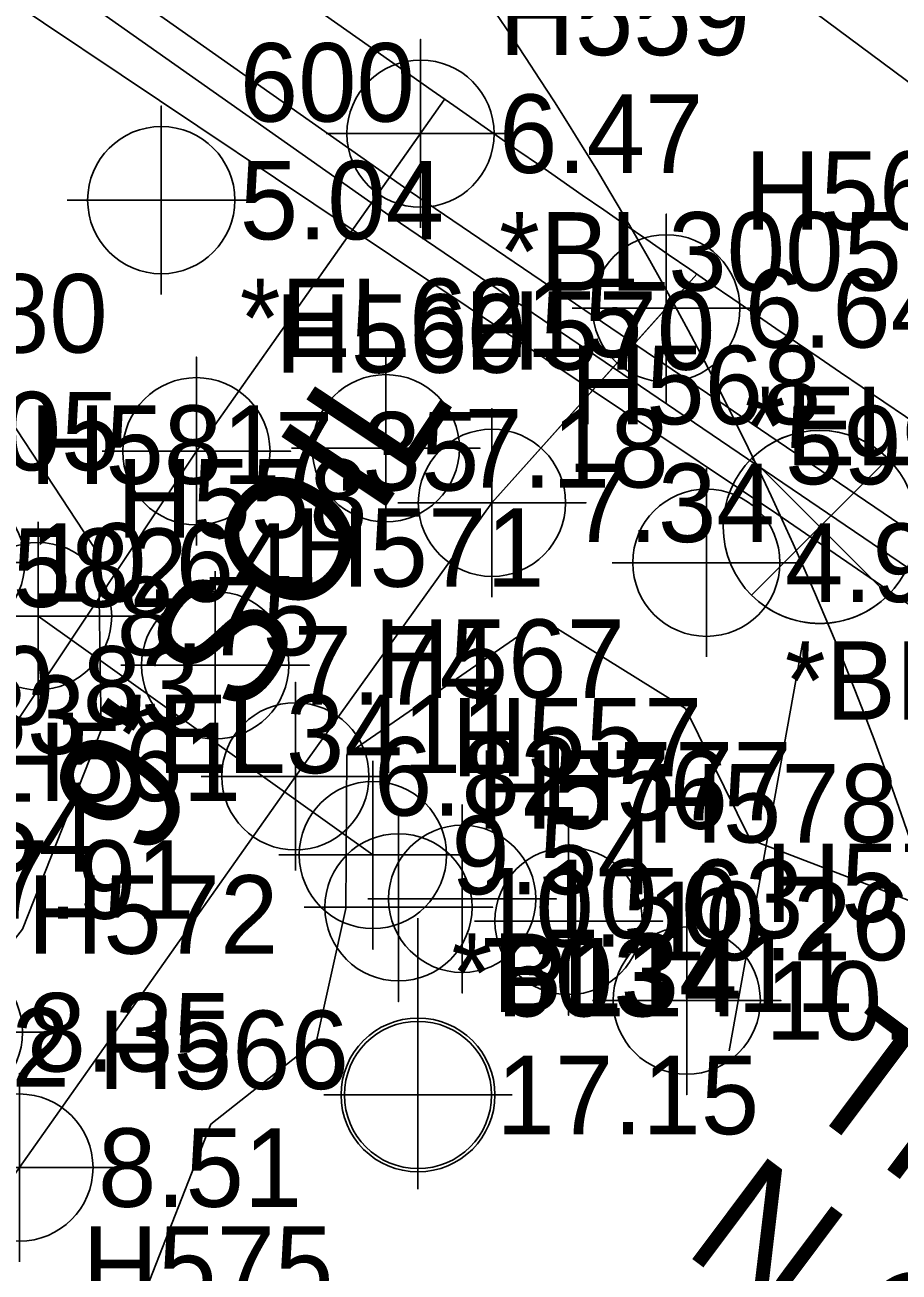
# Model space of a CAD drawing. Extents: x 2597630 to 2605918, y 617194 to 635093.
# Drawn here: x 2605052.23 to 2605080.06, y 618492.94 to 618532.66 of the extents above; entities that cross this region are included whole.
import ezdxf

# ---------------------------------------------------------------- set-up
doc = ezdxf.new("R2010")
doc.units = 0
for name, color, linetype in [('COGO Default Chain', 7, 'Continuous'), ('COGO Default Curve', 7, 'Continuous'), ('Cogo Default Point CELL', 7, 'Continuous'), ('COGO Default Point Number', 7, 'Continuous'), ('Default Symbol Text', 7, 'Continuous'), ('Exist DTM Regular Point CELL', 7, 'Continuous'), ('Exist DTM Regular Point Cogo Elevation', 7, 'Continuous'), ('Exist DTM Regular Point Cogo Number', 7, 'Continuous'), ('Exist Horizontal Alignment', 7, 'Continuous'), ('Exist Other Culture Gate', 7, 'Continuous'), ('Exist Other Culture Gate Cogo Comment', 7, 'Continuous'), ('Exist Other Culture Gate Cogo Elevation', 7, 'Continuous'), ('Exist Other Culture Gate Cogo Number', 7, 'Continuous'), ('Exist Other Culture Gate Cogo Point CELL', 7, 'Continuous'), ('Exist Property Owner Text', 7, 'Continuous'), ('Exist Roads EOP', 7, 'Continuous'), ('Exist Roads Soil', 7, 'Continuous'), ('Exist Roads Soil Cogo Comment', 7, 'Continuous'), ('Exist Roads Soil Cogo Elevation', 7, 'Continuous'), ('Exist Roads Soil Cogo Number', 7, 'Continuous'), ('Exist Roads Soil Cogo Point CELL', 7, 'Continuous'), ('Exist Roads Soil Text', 7, 'Continuous'), ('Exist Structure Minor Pipes HDPE 15 Inch Cogo Comment', 7, 'Continuous'), ('Exist Structure Minor Pipes HDPE 15 Inch Cogo Elevation', 7, 'Continuous'), ('Exist Structure Minor Pipes HDPE 15 Inch Cogo Number', 7, 'Continuous'), ('Exist Structure Minor Pipes HDPE 15 Inch Cogo Point CELL', 7, 'Continuous'), ('Exist Structure Minor Pipes HDPE 18 Inch Cogo Point CELL', 7, 'Continuous'), ('Exist Utilities Power Pole CELL', 7, 'Continuous'), ('Exist Utilities Power Pole Cogo Elevation', 7, 'Continuous'), ('Exist Utilities Power Pole Cogo Number', 7, 'Continuous'), ('Exist Utilities Telephone UG Cable SUE LOS C', 7, 'Continuous'), ('Exist Utilities Water Test Hole SUE LOS A CELL', 7, 'Continuous'), ('Exist Utilities Water Test Hole SUE LOS A Leader', 7, 'Continuous'), ('Exist Utilities Water Test Hole SUE LOS A Text', 7, 'Continuous'), ('Exist Utilities Water UG Line SUE LOS B', 7, 'Continuous'), ('Exist Vegetation Woods Line', 7, 'Continuous'), ('Raster_Level_3', 7, 'Continuous')]:
    doc.layers.add(name, color=color, linetype=linetype)

# ---------------------------------------------------------------- blocks, each defined once
blk = doc.blocks.new('EXIST OTHER CULTURE GATE COGO POINT')
at = {"layer": 'Exist Other Culture Gate Cogo Point CELL'}
blk.add_lwpolyline([(0, 0.06), (0, -0.06), (0, 0), (0.06, 0), (-0.06, 0)], dxfattribs=at)
blk.add_circle((0, 0), 0.04688, dxfattribs=at)
blk = doc.blocks.new('EXIST ROADS SOIL COGO POINT')
at = {"layer": 'Exist Roads Soil Cogo Point CELL'}
blk.add_lwpolyline([(0, -0.06), (0, 0.06), (0, 0), (0.06, 0), (-0.06, 0)], dxfattribs=at)
blk.add_circle((0, 0), 0.04688, dxfattribs=at)
blk = doc.blocks.new('EXIST DTM REGULAR POINT')
at = {"layer": 'Exist DTM Regular Point CELL'}
blk.add_lwpolyline([(0, 0.06), (0, -0.06), (0, 0), (0.06, 0), (-0.06, 0)], dxfattribs=at)
blk.add_circle((0, 0), 0.04688, dxfattribs=at)
blk = doc.blocks.new('COGO DEFAULT POINT')
at = {"layer": 'Cogo Default Point CELL'}
for points in [[(0, 0.06), (0, 0)], [(-0.06, 0), (0, 0)], [(0, 0), (0.06, 0)], [(0, 0), (0, -0.06)]]:
    blk.add_lwpolyline(points, dxfattribs=at)
blk.add_circle((0, 0), 0.04688, dxfattribs=at)
blk = doc.blocks.new('EXIST STRUCTURE MINOR PIPES HDPE COGO POINT')
at = {"layer": 'Exist Structure Minor Pipes HDPE 18 Inch Cogo Point CELL'}
blk.add_lwpolyline([(-0.06, 0), (0.06, 0), (0, 0), (0, 0.06), (0, -0.06)], dxfattribs=at)
blk.add_circle((0, 0), 0.04688, dxfattribs=at)
blk = doc.blocks.new('EXIST UTILITIES WATER TEST HOLE SUE LOS A')
at = {"layer": 'Exist Utilities Water Test Hole SUE LOS A CELL'}
for points in [[(0.04348, 0.04348), (-0.04348, -0.04348), (0, 0), (-0.04348, 0.04348), (0.04348, -0.04348)], [(-0.04348, 0.04348), (0, 0), (0.04348, 0.04348)], [(0.04348, -0.04348), (0, 0), (-0.04348, -0.04348)]]:
    blk.add_lwpolyline(points, dxfattribs=at)
blk.add_circle((0, 0), 0.06149, dxfattribs=at)
for start, end in [(45, 135), (225, 315)]:
    blk.add_arc((0, 0), 0.06149, start, end, dxfattribs=at)

msp = doc.modelspace()

# ---------------------------------------------------------------- linework, layer by layer
at = {"layer": 'COGO Default Chain'}
msp.add_line((2604906.9, 618659.448), (2605092.435, 618521.9), dxfattribs=at)
msp.add_line((2604906.9, 618659.448), (2605092.435, 618521.9), dxfattribs=at)
msp.add_line((2604906.9, 618659.448), (2605092.435, 618521.9), dxfattribs=at)
for centre, radius, start, end in [((2605334.316, 619054.493), 571.893, 233.44825, 249.95735), ((2605334.316, 619054.493), 571.893, 233.44825, 249.95735), ((2605334.316, 619054.493), 571.893, 233.44825, 249.95735), ((2604976.371, 618471.014), 110, 356.74026, 53.44825)]:
    msp.add_arc(centre, radius, start, end, dxfattribs=at)
at = {"layer": 'COGO Default Curve'}
for centre, radius, start, end in [((2605334.316, 619054.493), 571.893, 233.44825, 249.95735), ((2605334.316, 619054.493), 571.893, 233.44825, 249.95735), ((2604976.371, 618471.014), 110, 356.74026, 53.44825)]:
    msp.add_arc(centre, radius, start, end, dxfattribs=at)
at = {"layer": 'Exist Horizontal Alignment'}
msp.add_line((2604906.9, 618659.448), (2605092.435, 618521.9), dxfattribs=at)
msp.add_arc((2605334.316, 619054.493), 571.893, 233.44825, 249.95735, dxfattribs=at)
at = {"layer": 'Exist Other Culture Gate'}
msp.add_line((2605063.307, 618506.225), (2605052.646, 618513.831), dxfattribs=at)
at = {"layer": 'Exist Roads EOP'}
for points in [[(2604973.794, 618621.175), (2605003.899, 618598.528), (2605046.196, 618567.408), (2605072.515, 618548.047), (2605103.618, 618527.364), (2605140.117, 618505.161), (2605178.033, 618485.562), (2605220.739, 618472.458), (2605259.093, 618465.195), (2605301.774, 618462.969), (2605350.348, 618466.747), (2605390.569, 618472.395), (2605430.003, 618479.657), (2605472.601, 618488.42), (2605517.963, 618498.678), (2605555.274, 618508.222)], [(2605554.931, 618488.691), (2605518.323, 618479.552), (2605476.771, 618470.314), (2605429.068, 618460.66), (2605388.393, 618453.139), (2605342.247, 618446.788), (2605297.978, 618443.933), (2605250.493, 618446.948), (2605224.746, 618451.291), (2605188.067, 618461.914), (2605143.175, 618481.98), (2605101.821, 618506.05), (2605057.725, 618535.842), (2605018.828, 618564.087), (2604984.62, 618589.304), (2604956.97, 618610.183)]]:
    msp.add_spline(points, degree=3, dxfattribs=at)
at = {"layer": 'Exist Roads Soil'}
for points in [[(2605065.58, 618530.268), (2605057.688, 618519.082), (2605048.619, 618505.442), (2605043.163, 618496.352), (2605035.146, 618482.448)], [(2605064.824, 618529.196), (2605057.688, 618519.082), (2605048.619, 618505.442), (2605043.163, 618496.352), (2605035.146, 618482.448)], [(2605041.659, 618478.711), (2605044.976, 618486.355), (2605052.051, 618496.27), (2605060.839, 618508.728), (2605067.097, 618517.44), (2605073.62, 618524.72)], [(2605041.659, 618478.711), (2605044.976, 618486.355), (2605052.051, 618496.27), (2605060.839, 618508.728), (2605067.097, 618517.44), (2605072.648, 618523.635)]]:
    msp.add_lwpolyline(points, dxfattribs=at)
at = {"layer": 'Exist Utilities Power Pole CELL'}
for q in [(2605064.743, 618504.208), (2605064.743, 618498.583)]:
    msp.add_line((2605064.743, 618498.583), q, dxfattribs=at)
msp.add_circle((2605064.743, 618498.583), 2.45, dxfattribs=at)
at = {"layer": 'Exist Utilities Telephone UG Cable SUE LOS C'}
for points in [[(2605035.066, 618529.174), (2605044.701, 618541.284), (2605064.459, 618527.372), (2605084.583, 618513.704), (2605100.475, 618503.765), (2605114.433, 618495.379), (2605124.434, 618489.604), (2605135.591, 618483.21), (2605148.008, 618476.685), (2605160.516, 618470.334), (2605171.841, 618465.29), (2605179.513, 618461.899), (2605191.486, 618457.352), (2605197.211, 618455.484), (2605216.999, 618449.631), (2605228.628, 618446.625), (2605244.658, 618443.836), (2605269.573, 618441.133), (2605291.807, 618441.133), (2605291.093, 618423.377)], [(2605035.567, 618529.349), (2605044.896, 618539.924), (2605063.89, 618526.549), (2605084.036, 618512.866), (2605099.952, 618502.912), (2605113.925, 618494.517), (2605123.935, 618488.737), (2605135.109, 618482.333), (2605147.549, 618475.796), (2605160.086, 618469.431), (2605171.435, 618464.376), (2605179.133, 618460.973), (2605191.153, 618456.408), (2605196.914, 618454.529), (2605216.732, 618448.667), (2605228.417, 618445.647), (2605244.518, 618442.845), (2605269.519, 618440.133), (2605290.766, 618440.133), (2605290.933, 618424.271)]]:
    msp.add_lwpolyline(points, dxfattribs=at)
at = {"layer": 'Exist Utilities Water Test Hole SUE LOS A Leader'}
msp.add_line((2605076.992, 618512.959), (2605074.653, 618499.985), dxfattribs=at)
at = {"layer": 'Exist Utilities Water UG Line SUE LOS B'}
msp.add_lwpolyline([(2604726.889, 618802.825), (2604728.623, 618800.62), (2604750.622, 618775.419), (2604790.386, 618735.469), (2604815.583, 618710.966), (2604846.421, 618684.691), (2604883.421, 618655.421), (2604920.609, 618626.25), (2604956.469, 618598.67), (2605000.193, 618568.419), (2605036.439, 618543.714), (2605076.168, 618517.089), (2605118.843, 618487.791), (2605146.777, 618472.232), (2605179.699, 618456.688), (2605215.856, 618442.587), (2605263.864, 618435.28), (2605306.639, 618434.129), (2605336.924, 618437.158), (2605382.69, 618444.237), (2605417.11, 618449.886), (2605451.772, 618457.953), (2605484.983, 618464.773), (2605522.806, 618473.788)], dxfattribs=at)
at = {"layer": 'Exist Vegetation Woods Line'}
for points in [[(2605008.378, 618506.807), (2605012.587, 618506.37), (2605016.286, 618506.626), (2605020.056, 618508.784), (2605020.809, 618511.897), (2605020.35, 618515.793), (2605019.182, 618520.278), (2605019.096, 618525.981), (2605021.77, 618527.822), (2605025.534, 618530.38), (2605031.707, 618532.474), (2605040.839, 618530.71), (2605042.97, 618528.741), (2605050.066, 618522.644), (2605054.572, 618515.807), (2605054.656, 618510.205), (2605052.15, 618503.863), (2605048.027, 618498.598), (2605040.205, 618486.372)], [(2605058.147, 618497.649), (2605061.51, 618500.302), (2605062.447, 618504.518), (2605062.473, 618509.422), (2605068.713, 618513.719), (2605073.258, 618510.885), (2605075.322, 618506.713), (2605082.87, 618503.825), (2605089.724, 618500.526), (2605093.583, 618496.782), (2605102.889, 618490.117), (2605107.952, 618486.191), (2605113.316, 618482.169), (2605117.958, 618479.537), (2605127.18, 618478.475), (2605135.936, 618475.104), (2605143.877, 618466.118), (2605148.07, 618460.077), (2605155.892, 618452.29), (2605161.358, 618448.169), (2605163.552, 618441.998), (2605163.627, 618436.996)], [(2605098.938, 618433.521), (2605098.759, 618438.722), (2605098.128, 618447.418), (2605099.728, 618454.147), (2605102.678, 618457.593), (2605107.208, 618462.464), (2605102.762, 618465.299), (2605097.053, 618465.714), (2605089.448, 618465.699), (2605081.047, 618465.373), (2605074.94, 618465.581), (2605062.828, 618465.899), (2605056.374, 618469.204), (2605053.117, 618472.858), (2605052.789, 618481.358), (2605055.063, 618489.798), (2605058.147, 618497.649)]]:
    msp.add_lwpolyline(points, dxfattribs=at)
at = {"layer": 'Raster_Level_3'}
msp.add_arc((2605333.954, 619054.76), 571.893, 233.49328, 249.99328, dxfattribs=at)

# ---------------------------------------------------------------- block references
at = {"layer": 'Cogo Default Point CELL', "xscale": 50, "yscale": 50}
msp.add_blockref('COGO DEFAULT POINT', (2605064.743, 618498.583), dxfattribs=at)
at = {"layer": 'Exist DTM Regular Point CELL', "xscale": 50, "yscale": 50}
for p in [(2605063.718, 618519.177), (2605049.876, 618515.541), (2605058.283, 618512.267), (2605066.15, 618504.828), (2605064.122, 618504.558), (2605069.538, 618504.122), (2605073.302, 618501.589), (2605049.807, 618500.579)]:
    msp.add_blockref('EXIST DTM REGULAR POINT', p, dxfattribs=at)
at = {"layer": 'Exist Other Culture Gate Cogo Point CELL', "xscale": 50, "yscale": 50}
for p in [(2605052.646, 618513.831), (2605052.646, 618513.831), (2605063.307, 618506.225), (2605063.307, 618506.225)]:
    msp.add_blockref('EXIST OTHER CULTURE GATE COGO POINT', p, dxfattribs=at)
at = {"layer": 'Exist Roads Soil Cogo Point CELL', "xscale": 50, "yscale": 50}
for p in [(2605064.824, 618529.196), (2605064.824, 618529.196), (2605064.824, 618529.196), (2605072.648, 618523.635), (2605072.648, 618523.635), (2605072.648, 618523.635), (2605057.688, 618519.082), (2605057.688, 618519.082), (2605057.688, 618519.082), (2605067.097, 618517.44), (2605067.097, 618517.44), (2605067.097, 618517.44), (2605060.839, 618508.728), (2605060.839, 618508.728), (2605060.839, 618508.728), (2605052.051, 618496.27), (2605052.051, 618496.27), (2605052.051, 618496.27)]:
    msp.add_blockref('EXIST ROADS SOIL COGO POINT', p, dxfattribs=at)
at = {"layer": 'Exist Structure Minor Pipes HDPE 15 Inch Cogo Point CELL', "xscale": 50, "yscale": 50}
for p in [(2605056.568, 618527.079), (2605056.568, 618527.079), (2605073.926, 618515.532), (2605073.926, 618515.532)]:
    msp.add_blockref('EXIST STRUCTURE MINOR PIPES HDPE COGO POINT', p, dxfattribs=at)
at = {"layer": 'Exist Utilities Water Test Hole SUE LOS A CELL', "xscale": 50, "yscale": 50}
msp.add_blockref('EXIST UTILITIES WATER TEST HOLE SUE LOS A', (2605077.539, 618516.672), dxfattribs=at)

# ---------------------------------------------------------------- texts
at = {"layer": 'COGO Default Point Number'}
msp.add_text('P114', height=2.5, dxfattribs=at).set_placement((2605067.243, 618501.083))
at = {"layer": 'Default Symbol Text'}
msp.add_text("LOW WIRE=28.61'", height=4, rotation=323.4482, dxfattribs=at).set_placement((2605054.036, 618553.802))
at = {"layer": 'Exist DTM Regular Point Cogo Elevation'}
for s, p in [('10.05', (2605046.87, 618518.473)), ('7.18', (2605066.218, 618517.927)), ('10.64', (2605052.376, 618514.291)), ('7.74', (2605060.783, 618511.017)), ('10.83', (2605049.418, 618510.373)), ('10.54', (2605046.158, 618505.69)), ('10.50', (2605066.622, 618503.308)), ('10.63', (2605068.65, 618503.578)), ('10.26', (2605072.038, 618502.872)), ('10.48', (2605075.802, 618500.339)), ('8.35', (2605052.307, 618499.329))]:
    msp.add_text(s, height=2.5, dxfattribs=at).set_placement(p)
at = {"layer": 'Exist DTM Regular Point Cogo Number'}
for s, p in [('H580', (2605046.87, 618522.223)), ('H570', (2605066.218, 618521.677)), ('H581', (2605052.376, 618518.041)), ('H571', (2605060.783, 618514.767)), ('H582', (2605049.418, 618514.123)), ('H583', (2605046.158, 618509.44)), ('H577', (2605068.65, 618507.328)), ('H576', (2605066.622, 618507.058)), ('H578', (2605072.038, 618506.622)), ('H579', (2605075.802, 618504.089)), ('H572', (2605052.307, 618503.079)), ('H575', (2605054.054, 618491.9))]:
    msp.add_text(s, height=2.5, dxfattribs=at).set_placement(p)
at = {"layer": 'Exist Other Culture Gate Cogo Comment'}
for s, p in [('*EL3411', (2605055.146, 618508.831)), ('*EL3411', (2605055.146, 618508.831)), ('*BL3411', (2605065.807, 618501.225)), ('*BL3411', (2605065.807, 618501.225))]:
    msp.add_text(s, height=2.5, dxfattribs=at).set_placement(p)
at = {"layer": 'Exist Other Culture Gate Cogo Elevation'}
for s, p in [('8.75', (2605055.146, 618512.581)), ('8.75', (2605055.146, 618512.581)), ('9.54', (2605065.807, 618504.975)), ('9.54', (2605065.807, 618504.975))]:
    msp.add_text(s, height=2.5, dxfattribs=at).set_placement(p)
at = {"layer": 'Exist Other Culture Gate Cogo Number'}
for s, p in [('H558', (2605055.146, 618516.331)), ('H558', (2605055.146, 618516.331)), ('H557', (2605065.807, 618508.725)), ('H557', (2605065.807, 618508.725))]:
    msp.add_text(s, height=2.5, dxfattribs=at).set_placement(p)
at = {"layer": 'Exist Property Owner Text'}
msp.add_text('NC DEPT OF TRANSPORTATION', height=5, rotation=323.4482, dxfattribs=at).set_placement((2605016.266, 618492.402))
at = {"layer": 'Exist Roads Soil Cogo Comment'}
for s, p in [('*BL3005', (2605067.324, 618524.196)), ('*BL3005', (2605067.324, 618524.196)), ('*EL3005', (2605075.148, 618518.635)), ('*EL3005', (2605075.148, 618518.635))]:
    msp.add_text(s, height=2.5, dxfattribs=at).set_placement(p)
at = {"layer": 'Exist Roads Soil Cogo Elevation'}
for s, p in [('6.47', (2605067.324, 618527.946)), ('6.47', (2605067.324, 618527.946)), ('6.64', (2605075.148, 618522.385)), ('6.64', (2605075.148, 618522.385)), ('7.35', (2605060.188, 618517.832)), ('7.35', (2605060.188, 618517.832)), ('7.34', (2605069.597, 618516.19)), ('7.34', (2605069.597, 618516.19)), ('6.82', (2605063.339, 618507.478)), ('6.82', (2605063.339, 618507.478)), ('7.91', (2605051.119, 618504.192)), ('7.91', (2605051.119, 618504.192)), ('8.51', (2605054.551, 618495.02)), ('8.51', (2605054.551, 618495.02))]:
    msp.add_text(s, height=2.5, dxfattribs=at).set_placement(p)
at = {"layer": 'Exist Roads Soil Cogo Number'}
for s, p in [('H559', (2605067.324, 618531.696)), ('H559', (2605067.324, 618531.696)), ('H569', (2605075.148, 618526.135)), ('H569', (2605075.148, 618526.135)), ('H560', (2605060.188, 618521.582)), ('H560', (2605060.188, 618521.582)), ('H568', (2605069.597, 618519.94)), ('H568', (2605069.597, 618519.94)), ('H567', (2605063.339, 618511.228)), ('H567', (2605063.339, 618511.228)), ('H561', (2605051.119, 618507.942)), ('H561', (2605051.119, 618507.942)), ('H562', (2605045.663, 618498.852)), ('H562', (2605045.663, 618498.852)), ('H566', (2605054.551, 618498.77)), ('H566', (2605054.551, 618498.77))]:
    msp.add_text(s, height=2.5, dxfattribs=at).set_placement(p)
at = {"layer": 'Exist Roads Soil Text'}
msp.add_text("9' SOIL", height=4, rotation=56.3808, dxfattribs=at).set_placement((2605056.14, 618505.916))
at = {"layer": 'Exist Structure Minor Pipes HDPE 15 Inch Cogo Comment'}
for s, p in [('*EL6215', (2605059.068, 618522.079)), ('*BL6215', (2605076.426, 618510.532))]:
    msp.add_text(s, height=2.5, dxfattribs=at).set_placement(p)
at = {"layer": 'Exist Structure Minor Pipes HDPE 15 Inch Cogo Elevation'}
for s, p in [('5.04', (2605059.068, 618525.829)), ('4.94', (2605076.426, 618514.282))]:
    msp.add_text(s, height=2.5, dxfattribs=at).set_placement(p)
at = {"layer": 'Exist Structure Minor Pipes HDPE 15 Inch Cogo Number'}
for s, p in [('600', (2605059.068, 618529.579)), ('599', (2605076.426, 618518.032))]:
    msp.add_text(s, height=2.5, dxfattribs=at).set_placement(p)
at = {"layer": 'Exist Utilities Power Pole Cogo Elevation'}
msp.add_text('17.15', height=2.5, dxfattribs=at).set_placement((2605067.243, 618497.333))
at = {"layer": 'Exist Utilities Power Pole Cogo Number'}
msp.add_text('603', height=2.5, dxfattribs=at).set_placement((2605067.243, 618501.083))
at = {"layer": 'Exist Utilities Water Test Hole SUE LOS A Text'}
for s, p in [('TH #2', (2605076.721, 618498.425)), ('N 618516.67', (2605073.126, 618493.621))]:
    msp.add_text(s, height=4, rotation=323.1889, dxfattribs=at).set_placement(p)

doc.saveas('drawing.dxf')
